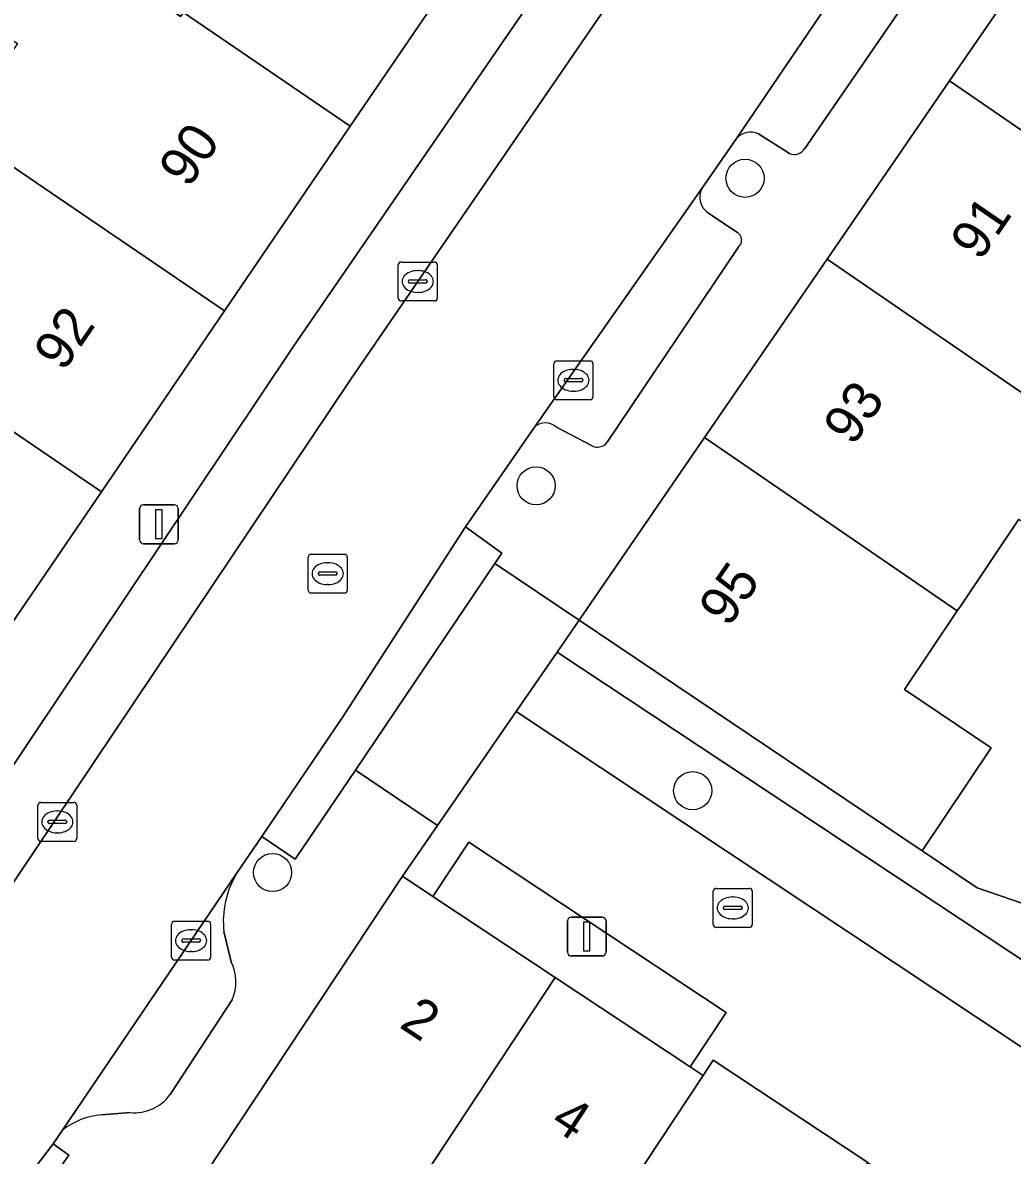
# Model space of a CAD drawing. Extents: x 159279 to 160377, y 384531 to 385888.
# Drawn here: x 159855.72 to 159881.12, y 384867.95 to 384897.02 of the extents above; entities that cross this region are included whole.
import ezdxf

# ---------------------------------------------------------------- set-up
doc = ezdxf.new("R2010")
doc.units = 0
for name, color, linetype in [('IMGEO_Boom', 7, 'Continuous'), ('IMGEO_Erf', 7, 'Continuous'), ('IMGEO_Kolk', 7, 'Continuous'), ('IMGEO_Lichtmast', 7, 'Continuous'), ('IMGEO_Muur', 7, 'Continuous'), ('IMGEO_Pand', 7, 'Continuous'), ('IMGEO_Pand_nummerreeks', 7, 'Continuous'), ('IMGEO_Parkeervlak_open', 7, 'Continuous'), ('IMGEO_Rijbaan_lokaal_open', 7, 'Continuous'), ('IMGEO_Rioolput', 7, 'Continuous'), ('IMGEO_Voetpad_open', 7, 'Continuous')]:
    doc.layers.add(name, color=color, linetype=linetype)

msp = doc.modelspace()

# ---------------------------------------------------------------- linework, layer by layer
at = {"layer": 'IMGEO_Boom'}
for centre in [(159874.259, 384893.023), (159868.898, 384885.13), (159872.916, 384877.305), (159862.135, 384875.204)]:
    msp.add_circle(centre, 0.489, dxfattribs=at)
at = {"layer": 'IMGEO_Erf'}
msp.add_lwpolyline([(159881.287, 384884.272), (159879.814, 384882.079), (159879.706, 384881.92), (159878.349, 384879.898), (159880.577, 384878.401), (159878.806, 384875.764), (159880.22, 384874.815), (159888.962, 384871.806)], dxfattribs=at)
at = {"layer": 'IMGEO_Kolk'}
for p, q in [((159865.361, 384889.949), (159865.361, 384890.801)), ((159865.436, 384890.875), (159866.288, 384890.875)), ((159866.362, 384890.801), (159866.362, 384889.949)), ((159865.62, 384890.369), (159865.62, 384890.381)), ((159865.663, 384890.418), (159866.061, 384890.418)), ((159865.849, 384890.655), (159865.874, 384890.655)), ((159866.104, 384890.381), (159866.104, 384890.369)), ((159866.058, 384890.332), (159865.66, 384890.332)), ((159865.872, 384890.095), (159865.847, 384890.095)), ((159866.288, 384889.875), (159865.436, 384889.875)), ((159869.43, 384888.339), (159870.282, 384888.339)), ((159869.355, 384887.413), (159869.355, 384888.265)), ((159869.843, 384888.119), (159869.868, 384888.119)), ((159870.356, 384888.265), (159870.356, 384887.413)), ((159869.614, 384887.833), (159869.614, 384887.845)), ((159870.052, 384887.796), (159869.654, 384887.796)), ((159869.657, 384887.882), (159870.055, 384887.882)), ((159870.098, 384887.845), (159870.098, 384887.833)), ((159869.866, 384887.559), (159869.841, 384887.559)), ((159870.282, 384887.339), (159869.43, 384887.339)), ((159856.186, 384877.004), (159857.038, 384877.004)), ((159856.111, 384876.078), (159856.111, 384876.93)), ((159856.599, 384876.784), (159856.624, 384876.784)), ((159857.112, 384876.93), (159857.112, 384876.078)), ((159856.37, 384876.498), (159856.37, 384876.51)), ((159856.808, 384876.461), (159856.41, 384876.461)), ((159856.413, 384876.547), (159856.811, 384876.547)), ((159856.854, 384876.51), (159856.854, 384876.498)), ((159856.622, 384876.224), (159856.597, 384876.224)), ((159857.038, 384876.004), (159856.186, 384876.004)), ((159873.444, 384873.871), (159873.444, 384874.723)), ((159873.519, 384874.797), (159874.371, 384874.797)), ((159874.445, 384874.723), (159874.445, 384873.871)), ((159873.932, 384874.577), (159873.957, 384874.577)), ((159873.703, 384874.291), (159873.703, 384874.303)), ((159874.141, 384874.254), (159873.743, 384874.254)), ((159873.746, 384874.34), (159874.144, 384874.34)), ((159874.187, 384874.303), (159874.187, 384874.291)), ((159859.544, 384873.031), (159859.544, 384873.883)), ((159859.619, 384873.957), (159860.471, 384873.957)), ((159860.545, 384873.883), (159860.545, 384873.031)), ((159873.955, 384874.017), (159873.93, 384874.017)), ((159860.032, 384873.737), (159860.057, 384873.737)), ((159874.371, 384873.797), (159873.519, 384873.797)), ((159859.803, 384873.451), (159859.803, 384873.463)), ((159860.241, 384873.414), (159859.843, 384873.414)), ((159859.846, 384873.5), (159860.244, 384873.5)), ((159860.287, 384873.463), (159860.287, 384873.451)), ((159860.471, 384872.957), (159859.619, 384872.957)), ((159860.055, 384873.177), (159860.03, 384873.177))]:
    msp.add_line(p, q, dxfattribs=at)
for points in [[(159865.361, 384889.949), (159865.361, 384890.801)], [(159865.436, 384890.875), (159866.288, 384890.875)], [(159866.362, 384890.801), (159866.362, 384889.949)], [(159866.288, 384889.875), (159865.436, 384889.875)], [(159869.43, 384888.339), (159870.282, 384888.339)], [(159869.355, 384887.413), (159869.355, 384888.265)], [(159870.356, 384888.265), (159870.356, 384887.413)], [(159870.282, 384887.339), (159869.43, 384887.339)], [(159856.186, 384877.004), (159857.038, 384877.004)], [(159856.111, 384876.078), (159856.111, 384876.93)], [(159857.112, 384876.93), (159857.112, 384876.078)], [(159857.038, 384876.004), (159856.186, 384876.004)], [(159873.444, 384873.871), (159873.444, 384874.723)], [(159873.519, 384874.797), (159874.371, 384874.797)], [(159874.445, 384874.723), (159874.445, 384873.871)], [(159859.544, 384873.031), (159859.544, 384873.883)], [(159859.619, 384873.957), (159860.471, 384873.957)], [(159860.545, 384873.883), (159860.545, 384873.031)], [(159874.371, 384873.797), (159873.519, 384873.797)], [(159860.471, 384872.957), (159859.619, 384872.957)]]:
    msp.add_lwpolyline(points, dxfattribs=at)
for centre, radius, start, end in [((159865.438, 384890.799), 0.0765, 91.552, 178.448), ((159865.438, 384890.799), 0.0765, 91.552, 178.448), ((159866.286, 384890.799), 0.0765, 1.552, 88.448), ((159866.286, 384890.799), 0.0765, 1.552, 88.448), ((159865.66, 384890.378), 0.0403, 85.8775, 175.7526), ((159866.065, 384890.38), 0.0386, 1.7309, 96.639), ((159865.657, 384890.368), 0.0366, 178.938, 274.7102), ((159866.061, 384890.375), 0.043, 264.8664, 352.4533), ((159865.438, 384889.951), 0.0765, 181.552, 268.448), ((159865.438, 384889.951), 0.0765, 181.552, 268.448), ((159866.286, 384889.951), 0.0765, 271.552, 358.448), ((159866.286, 384889.951), 0.0765, 271.552, 358.448), ((159869.432, 384888.263), 0.0765, 91.552, 178.448), ((159869.432, 384888.263), 0.0765, 91.552, 178.448), ((159870.28, 384888.263), 0.0765, 1.552, 88.448), ((159870.28, 384888.263), 0.0765, 1.552, 88.448), ((159869.654, 384887.842), 0.0403, 85.8775, 175.7526), ((159869.651, 384887.832), 0.0366, 178.938, 274.7102), ((159870.055, 384887.839), 0.043, 264.8664, 352.4533), ((159870.059, 384887.844), 0.0386, 1.7309, 96.639), ((159869.432, 384887.415), 0.0765, 181.552, 268.448), ((159869.432, 384887.415), 0.0765, 181.552, 268.448), ((159870.28, 384887.415), 0.0765, 271.552, 358.448), ((159870.28, 384887.415), 0.0765, 271.552, 358.448), ((159856.188, 384876.928), 0.0765, 91.552, 178.448), ((159856.188, 384876.928), 0.0765, 91.552, 178.448), ((159857.036, 384876.928), 0.0765, 1.552, 88.448), ((159857.036, 384876.928), 0.0765, 1.552, 88.448), ((159856.41, 384876.507), 0.0403, 85.8775, 175.7526), ((159856.407, 384876.497), 0.0366, 178.938, 274.7102), ((159856.811, 384876.504), 0.043, 264.8664, 352.4533), ((159856.815, 384876.509), 0.0386, 1.7309, 96.639), ((159856.188, 384876.08), 0.0765, 181.552, 268.448), ((159856.188, 384876.08), 0.0765, 181.552, 268.448), ((159857.036, 384876.08), 0.0765, 271.552, 358.448), ((159857.036, 384876.08), 0.0765, 271.552, 358.448), ((159873.521, 384874.721), 0.0765, 91.552, 178.448), ((159873.521, 384874.721), 0.0765, 91.552, 178.448), ((159874.369, 384874.721), 0.0765, 1.552, 88.448), ((159874.369, 384874.721), 0.0765, 1.552, 88.448), ((159873.743, 384874.3), 0.0403, 85.8775, 175.7526), ((159873.74, 384874.29), 0.0366, 178.938, 274.7102), ((159874.144, 384874.297), 0.043, 264.8664, 352.4533), ((159874.148, 384874.302), 0.0386, 1.7309, 96.639), ((159859.621, 384873.881), 0.0765, 91.552, 178.448), ((159859.621, 384873.881), 0.0765, 91.552, 178.448), ((159860.469, 384873.881), 0.0765, 1.552, 88.448), ((159860.469, 384873.881), 0.0765, 1.552, 88.448), ((159873.521, 384873.873), 0.0765, 181.552, 268.448), ((159873.521, 384873.873), 0.0765, 181.552, 268.448), ((159874.369, 384873.873), 0.0765, 271.552, 358.448), ((159874.369, 384873.873), 0.0765, 271.552, 358.448), ((159859.843, 384873.46), 0.0403, 85.8775, 175.7526), ((159859.84, 384873.45), 0.0366, 178.938, 274.7102), ((159860.244, 384873.457), 0.043, 264.8664, 352.4533), ((159860.248, 384873.462), 0.0386, 1.7309, 96.639), ((159859.621, 384873.033), 0.0765, 181.552, 268.448), ((159859.621, 384873.033), 0.0765, 181.552, 268.448), ((159860.469, 384873.033), 0.0765, 271.552, 358.448), ((159860.469, 384873.033), 0.0765, 271.552, 358.448)]:
    msp.add_arc(centre, radius, start, end, dxfattribs=at)
for centre, major_axis, ratio, start_param, end_param in [((159865.848, 384890.375), (-0.387, 0.002), 0.722429, 4.712389, 7.853982), ((159865.873, 384890.375), (-0.39, 0.002), 0.717154, 1.570796, 4.712389), ((159869.842, 384887.839), (-0.387, 0.002), 0.722429, 4.712389, 7.853982), ((159869.867, 384887.839), (-0.39, 0.002), 0.717154, 1.570796, 4.712389), ((159856.598, 384876.504), (-0.387, 0.002), 0.722429, 4.712389, 7.853982), ((159856.623, 384876.504), (-0.39, 0.002), 0.717154, 1.570796, 4.712389), ((159873.931, 384874.297), (-0.387, 0.002), 0.722429, 4.712389, 7.853982), ((159873.956, 384874.297), (-0.39, 0.002), 0.717154, 1.570796, 4.712389), ((159860.031, 384873.457), (-0.387, 0.002), 0.722429, 4.712389, 7.853982), ((159860.056, 384873.457), (-0.39, 0.002), 0.717154, 1.570796, 4.712389)]:
    msp.add_ellipse(centre, major_axis=major_axis, ratio=ratio, start_param=start_param, end_param=end_param, dxfattribs=at)
at = {"layer": 'IMGEO_Lichtmast'}
for p, q in [((159858.823, 384884.645), (159859.613, 384884.645)), ((159859.613, 384884.645), (159858.823, 384884.645)), ((159858.723, 384883.745), (159858.723, 384884.545)), ((159858.723, 384884.545), (159858.723, 384883.745)), ((159859.713, 384884.545), (159859.713, 384883.745)), ((159859.713, 384883.745), (159859.713, 384884.545)), ((159859.613, 384883.645), (159858.823, 384883.645)), ((159858.823, 384883.645), (159859.613, 384883.645)), ((159869.702, 384873.162), (159869.702, 384873.962)), ((159869.702, 384873.962), (159869.702, 384873.162)), ((159869.802, 384874.062), (159870.592, 384874.062)), ((159870.592, 384874.062), (159869.802, 384874.062)), ((159870.692, 384873.962), (159870.692, 384873.162)), ((159870.692, 384873.162), (159870.692, 384873.962)), ((159870.592, 384873.062), (159869.802, 384873.062)), ((159869.802, 384873.062), (159870.592, 384873.062))]:
    msp.add_line(p, q, dxfattribs=at)
for points in [[(159859.143, 384884.52), (159859.293, 384884.52), (159859.293, 384883.77), (159859.143, 384883.77), (159859.143, 384884.52)], [(159870.122, 384873.937), (159870.272, 384873.937), (159870.272, 384873.187), (159870.122, 384873.187), (159870.122, 384873.937)]]:
    msp.add_lwpolyline(points, dxfattribs=at)
for centre, start, end in [((159858.823, 384884.545), 90, 180), ((159858.823, 384884.545), 90, 180), ((159859.613, 384884.545), 0, 90), ((159859.613, 384884.545), 360, 90), ((159858.823, 384883.745), 180, 270), ((159858.823, 384883.745), 180, 270), ((159859.613, 384883.745), 270, 0), ((159859.613, 384883.745), 270, 0), ((159869.802, 384873.962), 90, 180), ((159869.802, 384873.962), 90, 180), ((159870.592, 384873.962), 0, 90), ((159870.592, 384873.962), 360, 90), ((159869.802, 384873.162), 180, 270), ((159869.802, 384873.162), 180, 270), ((159870.592, 384873.162), 270, 0), ((159870.592, 384873.162), 270, 0)]:
    msp.add_arc(centre, 0.1, start, end, dxfattribs=at)
at = {"layer": 'IMGEO_Muur'}
msp.add_lwpolyline([(159888.962, 384871.806), (159880.22, 384874.815), (159878.806, 384875.764)], dxfattribs=at)
at = {"layer": 'IMGEO_Pand'}
for points in [[(159865.376, 384903.166), (159860.376, 384902.42), (159860.639, 384900.304), (159858.315, 384900.016), (159857.456, 384898.753), (159859.775, 384897.173), (159859.846, 384897.277), (159864.13, 384894.359), (159866.228, 384897.439)], [(159859.846, 384897.277), (159859.775, 384897.173), (159857.456, 384898.753), (159855.306, 384900.218), (159853.657, 384897.798), (159855.587, 384896.483), (159854.078, 384894.268), (159856.612, 384892.542), (159860.902, 384889.62), (159864.13, 384894.359)], [(159879.508, 384895.525), (159885.898, 384891.135), (159888.238, 384889.527), (159889.734, 384891.705), (159891.358, 384894.122), (159886.602, 384897.388), (159882.65, 384900.102)], [(159885.898, 384891.135), (159879.508, 384895.525), (159876.365, 384890.947), (159880.316, 384888.235), (159885.09, 384884.957), (159885.156, 384885.055), (159886.714, 384887.374), (159884.411, 384888.921)], [(159856.612, 384892.542), (159854.078, 384894.268), (159852.954, 384895.033), (159851.513, 384892.919), (159850.736, 384893.449), (159848.901, 384890.756), (159850.777, 384889.478), (159853.331, 384887.739), (159853.445, 384887.906), (159857.741, 384884.98), (159860.902, 384889.62)], [(159873.223, 384886.371), (159879.706, 384881.92), (159879.814, 384882.079), (159881.287, 384884.272), (159883.591, 384882.725), (159885.09, 384884.957), (159880.316, 384888.235), (159876.365, 384890.947)], [(159853.445, 384887.906), (159853.331, 384887.739), (159850.777, 384889.478), (159849.352, 384887.386), (159847.463, 384888.673), (159845.775, 384886.194), (159850.382, 384883.056), (159854.514, 384880.242), (159857.741, 384884.98)], [(159879.706, 384881.92), (159873.223, 384886.371), (159870.001, 384881.679), (159878.806, 384875.764), (159880.577, 384878.401), (159878.349, 384879.898)], [(159869.385, 384872.512), (159866.249, 384874.589), (159865.466, 384875.107), (159859.566, 384866.198), (159857.649, 384863.408), (159861.699, 384860.634), (159861.956, 384861.023), (159863.203, 384862.907), (159863.609, 384863.521), (159862.096, 384864.523), (159863.456, 384866.576), (159863.735, 384866.992), (159865.132, 384866.067)], [(159873.182, 384869.998), (159872.848, 384870.219), (159869.385, 384872.512), (159865.132, 384866.067), (159866.56, 384865.123), (159866.716, 384865.02), (159866.877, 384864.914), (159865.165, 384862.327), (159867.218, 384860.968)], [(159877.41, 384867.765), (159873.443, 384870.392), (159873.182, 384869.998), (159867.218, 384860.968), (159869.159, 384859.683), (159870.861, 384862.255), (159871.377, 384861.913), (159872.888, 384860.913)]]:
    msp.add_lwpolyline(points, close=True, dxfattribs=at)
at = {"layer": 'IMGEO_Parkeervlak_open'}
for points in [[(159879.386, 384901.926), (159874.043, 384894.048)], [(159871.149, 384901.051), (159862.663, 384888.7), (159854.183, 384876.035)], [(159853.991, 384872.729), (159864.145, 384887.869), (159872.922, 384900.679)], [(159875.791, 384893.792), (159880.322, 384900.373)], [(159874.601, 384894.169), (159875.4, 384893.658)], [(159873.15, 384892.763), (159868.854, 384886.639)], [(159874.046, 384891.643), (159873.323, 384892.131)], [(159870.72, 384886.247), (159874.079, 384891.244)], [(159869.423, 384886.632), (159870.32, 384886.162)], [(159861.212, 384875.179), (159856.746, 384868.594)], [(159861.071, 384872.916), (159860.883, 384873.688)], [(159859.505, 384869.503), (159861.097, 384871.938)], [(159857.747, 384868.983), (159858.483, 384869.044)]]:
    msp.add_lwpolyline(points, dxfattribs=at)
msp.add_lwpolyline([(159869.439, 384880.864), (159868.384, 384879.335), (159897.457, 384860.028), (159897.716, 384859.856), (159898.765, 384861.44)], close=True, dxfattribs=at)
for centre, radius, start, end in [((159874.408, 384893.713), 0.495, 67.0512, 137.4187), ((159875.521, 384893.943), 0.309, 246.9722, 330.8621), ((159873.575, 384892.54), 0.48, 152.3076, 238.31), ((159873.929, 384891.432), 0.241, 308.5495, 60.9064), ((159869.135, 384886.313), 0.43, 47.8956, 130.6947), ((159870.473, 384886.428), 0.307, 240.1592, 323.8346), ((159863.313, 384873.934), 2.442, 149.339, 185.7743), ((159860.062, 384872.4), 1.133, 335.9444, 27.1013), ((159858.595, 384870.163), 1.124, 264.2979, 324.0736), ((159857.895, 384867.121), 1.868, 94.5328, 127.9406)]:
    msp.add_arc(centre, radius, start, end, dxfattribs=at)
at = {"layer": 'IMGEO_Rijbaan_lokaal_open'}
for points in [[(159855.857, 384867.389), (159856.504, 384868.243), (159856.746, 384868.594), (159861.212, 384875.179), (159861.857, 384876.131), (159863.938, 384879.199), (159867.088, 384884.077), (159868.854, 384886.639), (159873.15, 384892.763), (159874.043, 384894.048), (159879.386, 384901.926)], [(159872.922, 384900.679), (159864.145, 384887.869), (159853.991, 384872.729), (159843.797, 384857.764)]]:
    msp.add_lwpolyline(points, dxfattribs=at)
msp.add_lwpolyline([(159868.384, 384879.335), (159866.367, 384876.413), (159865.466, 384875.107), (159866.249, 384874.589), (159867.172, 384875.982), (159873.771, 384871.612), (159872.848, 384870.219), (159873.182, 384869.998), (159873.443, 384870.392), (159877.41, 384867.765), (159881.376, 384865.139), (159881.131, 384864.769), (159885.052, 384862.172), (159888.86, 384859.651), (159892.668, 384857.129), (159893.221, 384856.763), (159894.138, 384858.149), (159895.58, 384857.194), (159897.457, 384860.028)], close=True, dxfattribs=at)
at = {"layer": 'IMGEO_Rioolput'}
for p, q in [((159863.05, 384882.45), (159863.05, 384883.302)), ((159863.125, 384883.376), (159863.977, 384883.376)), ((159863.538, 384883.156), (159863.563, 384883.156)), ((159864.051, 384883.302), (159864.051, 384882.45)), ((159863.309, 384882.87), (159863.309, 384882.882)), ((159863.747, 384882.833), (159863.349, 384882.833)), ((159863.352, 384882.919), (159863.75, 384882.919)), ((159863.793, 384882.882), (159863.793, 384882.87)), ((159863.561, 384882.596), (159863.536, 384882.596)), ((159863.977, 384882.376), (159863.125, 384882.376))]:
    msp.add_line(p, q, dxfattribs=at)
for points in [[(159863.05, 384882.45), (159863.05, 384883.302)], [(159863.125, 384883.376), (159863.977, 384883.376)], [(159864.051, 384883.302), (159864.051, 384882.45)], [(159863.977, 384882.376), (159863.125, 384882.376)]]:
    msp.add_lwpolyline(points, dxfattribs=at)
for centre, radius, start, end in [((159863.127, 384883.3), 0.0765, 91.552, 178.448), ((159863.127, 384883.3), 0.0765, 91.552, 178.448), ((159863.975, 384883.3), 0.0765, 1.552, 88.448), ((159863.975, 384883.3), 0.0765, 1.552, 88.448), ((159863.349, 384882.879), 0.0403, 85.8775, 175.7526), ((159863.346, 384882.869), 0.0366, 178.938, 274.7102), ((159863.75, 384882.876), 0.043, 264.8664, 352.4533), ((159863.754, 384882.881), 0.0386, 1.7309, 96.639), ((159863.127, 384882.452), 0.0765, 181.552, 268.448), ((159863.127, 384882.452), 0.0765, 181.552, 268.448), ((159863.975, 384882.452), 0.0765, 271.552, 358.448), ((159863.975, 384882.452), 0.0765, 271.552, 358.448)]:
    msp.add_arc(centre, radius, start, end, dxfattribs=at)
for centre, major_axis, ratio, start_param, end_param in [((159863.537, 384882.876), (-0.387, 0.002), 0.722429, 4.712389, 7.853982), ((159863.562, 384882.876), (-0.39, 0.002), 0.717154, 1.570796, 4.712389)]:
    msp.add_ellipse(centre, major_axis=major_axis, ratio=ratio, start_param=start_param, end_param=end_param, dxfattribs=at)
at = {"layer": 'IMGEO_Voetpad_open'}
for points in [[(159873.223, 384886.371), (159876.365, 384890.947), (159879.508, 384895.525), (159882.65, 384900.102), (159885.793, 384904.678), (159889.179, 384909.609), (159890.919, 384912.144), (159897.705, 384913.18), (159903.053, 384913.997), (159908.282, 384914.795), (159913.511, 384915.593), (159918.741, 384916.392), (159923.977, 384917.191), (159927.558, 384917.738), (159927.465, 384918.157), (159929.557, 384919.059), (159932.112, 384918.851), (159942.2, 384920.443), (159935.415, 384924.956), (159934.401, 384923.411), (159925.203, 384929.508), (159926.252, 384931.023)], [(159854.183, 384876.035), (159862.663, 384888.7), (159871.149, 384901.051)], [(159880.322, 384900.373), (159875.791, 384893.792)], [(159866.228, 384897.439), (159864.13, 384894.359), (159860.902, 384889.62), (159857.741, 384884.98), (159854.514, 384880.242), (159852.394, 384877.102), (159850.859, 384874.845), (159849.964, 384874.912), (159848.679, 384873.022), (159847.394, 384871.133), (159847.784, 384870.326), (159846.748, 384868.804), (159845.847, 384868.871), (159845.673, 384868.614), (159845.499, 384868.359), (159845.895, 384867.538)], [(159875.4, 384893.658), (159874.601, 384894.169)], [(159874.043, 384894.048), (159873.15, 384892.763)], [(159873.323, 384892.131), (159874.046, 384891.643)], [(159874.079, 384891.244), (159870.72, 384886.247)], [(159868.854, 384886.639), (159867.088, 384884.077), (159868.014, 384883.399), (159867.838, 384883.138), (159870.001, 384881.679), (159873.223, 384886.371)], [(159870.32, 384886.162), (159869.423, 384886.632)], [(159865.466, 384875.107), (159866.367, 384876.413), (159864.26, 384877.834), (159862.719, 384875.549), (159861.857, 384876.131), (159861.212, 384875.179)], [(159859.566, 384866.198), (159865.466, 384875.107)], [(159860.883, 384873.688), (159861.071, 384872.916)], [(159861.097, 384871.938), (159859.505, 384869.503)], [(159858.483, 384869.044), (159857.747, 384868.983)], [(159856.746, 384868.594), (159856.504, 384868.243), (159856.909, 384867.951), (159853.369, 384862.905), (159852.964, 384863.197), (159852.628, 384862.693), (159851.84, 384861.549), (159851.738, 384861.379)]]:
    msp.add_lwpolyline(points, dxfattribs=at)
for points in [[(159867.838, 384883.138), (159868.014, 384883.399), (159867.088, 384884.077), (159863.938, 384879.199), (159861.857, 384876.131), (159862.719, 384875.549), (159864.26, 384877.834)], [(159868.384, 384879.335), (159869.439, 384880.864), (159870.001, 384881.679), (159867.838, 384883.138), (159864.26, 384877.834), (159866.367, 384876.413)], [(159888.95, 384869.106), (159890.199, 384870.983), (159888.962, 384871.806), (159880.22, 384874.815), (159878.806, 384875.764), (159870.001, 384881.679), (159869.439, 384880.864), (159898.765, 384861.44), (159901.691, 384859.502), (159916.111, 384850.031), (159920.816, 384846.869), (159921.765, 384846.256), (159924.875, 384844.2), (159943.718, 384831.713), (159942.677, 384830.134), (159945.658, 384828.169), (159946.698, 384829.747), (159977.441, 384809.465), (159978.078, 384810.424), (159973.48, 384813.451), (159954.748, 384825.784), (159953.493, 384826.611)], [(159867.172, 384875.982), (159866.249, 384874.589), (159869.385, 384872.512), (159872.848, 384870.219), (159873.771, 384871.612)], [(159852.964, 384863.197), (159853.369, 384862.905), (159856.909, 384867.951), (159856.504, 384868.243), (159855.857, 384867.389), (159855.264, 384866.519), (159854.241, 384865.11)]]:
    msp.add_lwpolyline(points, close=True, dxfattribs=at)
for centre, radius, start, end in [((159874.408, 384893.713), 0.495, 67.0512, 137.4187), ((159875.521, 384893.943), 0.309, 246.9722, 330.8621), ((159873.575, 384892.54), 0.48, 152.3076, 238.31), ((159873.929, 384891.432), 0.241, 308.5495, 60.9064), ((159869.135, 384886.313), 0.43, 47.8956, 130.6947), ((159870.473, 384886.428), 0.307, 240.1592, 323.8346), ((159863.313, 384873.934), 2.442, 149.339, 185.7743), ((159860.062, 384872.4), 1.133, 335.9444, 27.1013), ((159858.595, 384870.163), 1.124, 264.2979, 324.0736), ((159857.895, 384867.121), 1.868, 94.5328, 127.9406)]:
    msp.add_arc(centre, radius, start, end, dxfattribs=at)

# ---------------------------------------------------------------- texts
at = {"layer": 'IMGEO_Pand_nummerreeks'}
for s, rotation, p in [('90', 55.7373, (159859.981, 384892.745)), ('91', 55.5253, (159880.292, 384890.872)), ('92', 55.7373, (159856.772, 384888.034)), ('93', 55.5247, (159877.031, 384886.124)), ('95', 55.5253, (159873.835, 384881.469)), ('2', 326.5736, (159865.358, 384871.248)), ('4', 326.5736, (159869.223, 384868.696))]:
    msp.add_text(s, height=1, rotation=rotation, dxfattribs=at).set_placement(p)

doc.saveas('drawing.dxf')
